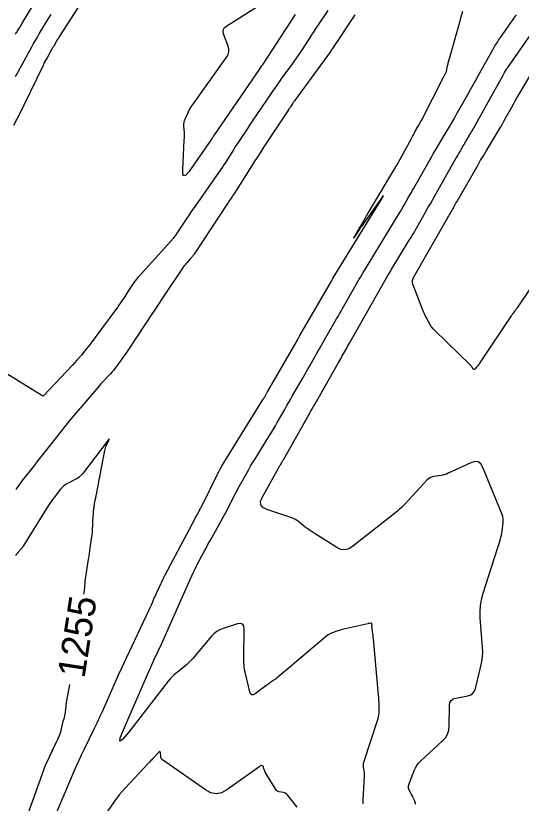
# Model space of a CAD drawing. Extents: x 658976 to 668726, y 639543 to 647196.
# Drawn here: x 661779.3 to 661889.7, y 641240.6 to 641412.7 of the extents above; entities that cross this region are included whole.
import ezdxf

# ---------------------------------------------------------------- set-up
doc = ezdxf.new("R2010")
doc.units = 0
for name, color, linetype in [('Ex_Contour Labels', 7, 'Continuous'), ('Ex_Major Contours', 7, 'Continuous'), ('Ex_Minor Contours', 7, 'Continuous')]:
    doc.layers.add(name, color=color, linetype=linetype)

msp = doc.modelspace()

# ---------------------------------------------------------------- linework, layer by layer
at = {"layer": 'Ex_Major Contours'}
for points in [[(661779.23, 641408.63), (661779.33, 641408.82), (661779.45, 641409.01), (661779.56, 641409.2), (661779.68, 641409.39), (661780.16, 641410.14), (661780.27, 641410.32), (661780.39, 641410.51), (661780.51, 641410.7), (661780.62, 641410.89), (661783.99, 641416.52)], [(661794.12, 641286.29), (661794.27, 641287.14), (661794.31, 641287.34), (661794.34, 641287.54), (661794.36, 641287.74), (661794.38, 641287.95), (661794.44, 641288.76), (661794.45, 641288.96), (661794.47, 641289.16), (661794.5, 641289.37), (661794.53, 641289.57), (661795.19, 641293.91), (661795.29, 641294.53), (661795.38, 641295.15), (661795.47, 641295.78), (661795.55, 641296.4), (661796.01, 641299.73), (661796.03, 641299.94), (661796.05, 641300.14), (661796.06, 641300.34), (661796.07, 641300.55), (661796.1, 641301.36), (661796.11, 641301.57), (661796.12, 641301.77), (661796.13, 641301.97), (661796.14, 641302.18), (661796.37, 641305.05), (661796.39, 641305.28), (661796.42, 641305.51), (661796.45, 641305.73), (661796.49, 641305.95), (661796.66, 641306.85), (661796.7, 641307.07), (661796.75, 641307.29), (661796.79, 641307.52), (661796.83, 641307.74), (661797.33, 641310.35), (661797.42, 641310.86), (661797.52, 641311.37), (661797.62, 641311.87), (661797.72, 641312.38), (661798.73, 641317.67), (661798.8, 641317.96), (661798.88, 641318.25), (661798.98, 641318.53), (661799.1, 641318.8), (661799.6, 641319.89), (661799.69, 641320.1), (661799.7, 641320.18), (661799.63, 641320.13), (661799.49, 641319.96), (661793.92, 641312.63), (661793.6, 641312.25), (661793.24, 641311.92), (661792.84, 641311.62), (661792.41, 641311.37), (661790.61, 641310.45), (661790.18, 641310.2), (661789.78, 641309.91), (661789.41, 641309.58), (661789.08, 641309.2), (661787.65, 641307.38), (661787.31, 641306.94), (661786.99, 641306.5), (661786.67, 641306.04), (661786.38, 641305.57), (661780.9, 641296.78), (661780.78, 641296.59), (661780.65, 641296.41), (661780.52, 641296.24), (661780.38, 641296.07), (661779.81, 641295.41), (661779.67, 641295.24), (661779.53, 641295.07), (661779.39, 641294.9), (661779.25, 641294.73)], [(661781.25, 641236.28), (661785.79, 641248.89), (661785.81, 641248.94), (661785.83, 641248.99), (661785.85, 641249.04), (661785.87, 641249.09), (661785.96, 641249.29), (661785.98, 641249.34), (661786, 641249.39), (661786.03, 641249.44), (661786.05, 641249.49), (661787.39, 641252.24), (661787.4, 641252.26), (661787.41, 641252.28), (661787.4, 641252.27), (661787.38, 641252.24), (661787.27, 641252.11), (661787.25, 641252.08), (661787.24, 641252.08), (661787.24, 641252.09), (661787.26, 641252.12), (661788.26, 641254.09), (661788.37, 641254.32), (661788.48, 641254.54), (661788.57, 641254.77), (661788.67, 641255), (661789.03, 641255.95), (661789.11, 641256.17), (661789.18, 641256.39), (661789.23, 641256.62), (661789.29, 641256.84), (661789.5, 641257.9), (661789.53, 641258.05), (661789.57, 641258.2), (661789.62, 641258.36), (661789.66, 641258.51), (661789.86, 641259.11), (661789.9, 641259.26), (661789.95, 641259.41), (661789.98, 641259.57), (661790.01, 641259.72), (661790.13, 641260.41), (661790.16, 641260.58), (661790.18, 641260.74), (661790.2, 641260.91), (661790.22, 641261.08), (661790.28, 641261.87), (661790.3, 641262.06), (661790.32, 641262.24), (661790.35, 641262.43), (661790.38, 641262.61), (661791.07, 641266.53)]]:
    msp.add_lwpolyline(points, dxfattribs=at)
at = {"layer": 'Ex_Minor Contours'}
for points in [[(661778.89, 641388.8), (661779.3, 641389.6), (661779.4, 641389.8), (661779.5, 641390), (661779.6, 641390.2), (661779.7, 641390.41), (661785.33, 641401.91), (661785.52, 641402.29), (661785.71, 641402.66), (661785.91, 641403.03), (661786.11, 641403.4), (661787.02, 641405.07), (661787.17, 641405.34), (661787.33, 641405.61), (661787.48, 641405.88), (661787.64, 641406.14), (661788.27, 641407.2), (661788.43, 641407.46), (661788.59, 641407.72), (661788.75, 641407.98), (661788.92, 641408.24), (661794.52, 641416.94)], [(661840.32, 641412.99), (661833.08, 641401.88), (661833.04, 641401.82), (661833, 641401.76), (661832.96, 641401.7), (661832.92, 641401.64), (661832.75, 641401.42), (661832.71, 641401.36), (661832.67, 641401.3), (661832.63, 641401.25), (661832.59, 641401.19), (661822.57, 641386.49), (661822.54, 641386.43), (661822.5, 641386.37), (661822.46, 641386.32), (661822.43, 641386.26), (661822.26, 641386.01), (661822.23, 641385.97), (661822.2, 641385.92), (661822.18, 641385.88), (661822.15, 641385.83), (661822.03, 641385.66), (661822.01, 641385.61), (661821.98, 641385.57), (661821.95, 641385.52), (661821.92, 641385.48), (661817.06, 641378.56), (661816.45, 641377.84), (661816.03, 641377.67), (661815.8, 641378.06), (661815.77, 641379.01), (661816.1, 641385.6), (661816.12, 641385.98), (661816.12, 641386.37), (661816.12, 641386.75), (661816.11, 641387.13), (661816.03, 641388.65), (661816.03, 641389.03), (661816.08, 641389.4), (661816.17, 641389.76), (661816.3, 641390.11), (661816.99, 641391.67), (661817.17, 641392.04), (661817.36, 641392.4), (661817.58, 641392.75), (661817.81, 641393.09), (661825.39, 641403.69), (661825.71, 641404.25), (661825.86, 641404.83), (661825.86, 641405.42), (661825.69, 641406.04), (661824.73, 641408.55), (661824.59, 641409.14), (661824.65, 641409.67), (661824.91, 641410.12), (661825.38, 641410.52), (661831.73, 641414.52)], [(661847.46, 641413.86), (661845.34, 641410.68), (661844.86, 641409.95), (661844.38, 641409.23), (661843.9, 641408.5), (661843.43, 641407.77), (661841.53, 641404.86), (661841.05, 641404.13), (661840.56, 641403.42), (661840.06, 641402.7), (661839.56, 641402), (661837.37, 641399.01), (661836.84, 641398.27), (661836.32, 641397.53), (661835.8, 641396.79), (661835.28, 641396.04), (661831.7, 641390.79), (661831.24, 641390.11), (661830.78, 641389.43), (661830.33, 641388.74), (661829.88, 641388.06), (661827.88, 641385.01), (661827.53, 641384.47), (661827.17, 641383.93), (661826.82, 641383.38), (661826.48, 641382.83), (661825.09, 641380.64), (661824.74, 641380.09), (661824.38, 641379.55), (661824.02, 641379.01), (661823.65, 641378.48), (661818.46, 641371.1), (661817.97, 641370.4), (661817.49, 641369.69), (661817.01, 641368.98), (661816.53, 641368.26), (661814.64, 641365.4), (661814.16, 641364.7), (661813.65, 641364.01), (661813.11, 641363.35), (661812.54, 641362.7), (661806.22, 641355.79), (661805.92, 641355.45), (661805.64, 641355.1), (661805.36, 641354.73), (661805.1, 641354.36), (661804.09, 641352.85), (661803.83, 641352.47), (661803.58, 641352.09), (661803.33, 641351.71), (661803.08, 641351.33), (661802.02, 641349.73), (661801.75, 641349.34), (661801.49, 641348.95), (661801.21, 641348.57), (661800.93, 641348.18), (661795.51, 641340.92), (661794.58, 641339.71), (661793.62, 641338.53), (661792.62, 641337.38), (661791.59, 641336.26), (661785.31, 641329.6), (661785.3, 641329.59), (661785.27, 641329.55), (661785.27, 641329.55), (661785.26, 641329.55), (661785.26, 641329.55), (661785.25, 641329.55), (661785.09, 641329.65), (661785.06, 641329.67), (661785.03, 641329.69), (661785, 641329.71), (661784.98, 641329.72), (661761.21, 641344.31)], [(661779.25, 641399.39), (661779.56, 641399.99), (661779.89, 641400.59), (661782.78, 641405.87), (661783.19, 641406.59), (661783.59, 641407.31), (661784.01, 641408.03), (661784.43, 641408.74), (661786.42, 641412.06), (661786.7, 641412.53), (661786.99, 641412.99)], [(661853.39, 641412.92), (661848.45, 641405.5), (661848.42, 641405.45), (661848.39, 641405.41), (661848.36, 641405.36), (661848.34, 641405.32), (661848.22, 641405.14), (661848.19, 641405.09), (661848.16, 641405.05), (661848.13, 641405.01), (661848.1, 641404.96), (661840.17, 641394.09), (661840.05, 641393.94), (661839.94, 641393.78), (661839.83, 641393.62), (661839.72, 641393.46), (661839.28, 641392.81), (661839.17, 641392.65), (661839.06, 641392.49), (661838.95, 641392.33), (661838.84, 641392.16), (661833.5, 641384.01), (661832.82, 641382.97), (661832.14, 641381.93), (661831.47, 641380.88), (661830.8, 641379.83), (661827.06, 641373.9), (661826.94, 641373.71), (661826.81, 641373.52), (661826.69, 641373.33), (661826.56, 641373.15), (661826.04, 641372.41), (661825.91, 641372.23), (661825.78, 641372.04), (661825.66, 641371.86), (661825.53, 641371.67), (661818.23, 641360.59), (661818.05, 641360.33), (661817.86, 641360.08), (661817.67, 641359.84), (661817.46, 641359.61), (661816.62, 641358.69), (661816.41, 641358.45), (661816.22, 641358.21), (661816.03, 641357.96), (661815.85, 641357.71), (661811.27, 641350.86), (661810.45, 641349.63), (661809.63, 641348.41), (661808.81, 641347.18), (661807.99, 641345.94), (661803.46, 641339.09), (661803.16, 641338.65), (661802.85, 641338.21), (661802.54, 641337.77), (661802.23, 641337.34), (661800.9, 641335.57), (661800.6, 641335.17), (661800.28, 641334.78), (661799.96, 641334.41), (661799.62, 641334.04), (661798.25, 641332.58), (661797.9, 641332.22), (661797.57, 641331.85), (661797.24, 641331.47), (661796.91, 641331.09), (661792.43, 641325.86), (661791.6, 641324.89), (661790.79, 641323.91), (661789.99, 641322.92), (661789.2, 641321.92), (661785.62, 641317.37), (661785.05, 641316.64), (661784.48, 641315.92), (661783.91, 641315.19), (661783.34, 641314.47), (661780.67, 641311.09), (661780.3, 641310.6), (661779.94, 641310.11), (661779.6, 641309.6), (661779.26, 641309.08)], [(661788, 641238.12), (661792.04, 641247.56), (661792.57, 641248.77), (661793.11, 641249.97), (661793.66, 641251.16), (661794.23, 641252.34), (661796.57, 641257.13), (661797.12, 641258.28), (661797.67, 641259.44), (661798.2, 641260.61), (661798.72, 641261.78), (661800.77, 641266.48), (661801.29, 641267.65), (661801.81, 641268.82), (661802.35, 641269.98), (661802.89, 641271.14), (661808.34, 641282.71), (661808.63, 641283.34), (661808.92, 641283.96), (661809.2, 641284.59), (661809.48, 641285.21), (661810.6, 641287.73), (661810.88, 641288.35), (661811.18, 641288.98), (661811.48, 641289.59), (661811.8, 641290.2), (661818.45, 641302.82), (661818.56, 641303.02), (661818.67, 641303.22), (661818.78, 641303.42), (661818.89, 641303.62), (661819.34, 641304.43), (661819.45, 641304.63), (661819.56, 641304.83), (661819.67, 641305.03), (661819.77, 641305.24), (661823.68, 641313.11), (661823.73, 641313.22), (661823.79, 641313.33), (661823.85, 641313.44), (661823.91, 641313.55), (661824.14, 641313.97), (661824.2, 641314.08), (661824.27, 641314.19), (661824.33, 641314.29), (661824.39, 641314.4), (661833.36, 641328.9), (661833.45, 641329.04), (661833.52, 641329.17), (661833.6, 641329.3), (661833.68, 641329.43), (661833.98, 641329.97), (661834.06, 641330.11), (661834.14, 641330.24), (661834.21, 641330.38), (661834.29, 641330.51), (661840.8, 641341.77), (661840.85, 641341.85), (661840.9, 641341.94), (661840.94, 641342.02), (661840.99, 641342.11), (661841.18, 641342.45), (661841.23, 641342.53), (661841.28, 641342.62), (661841.33, 641342.7), (661841.38, 641342.78), (661848.25, 641354.66), (661848.27, 641354.7), (661848.29, 641354.74), (661848.31, 641354.78), (661848.34, 641354.82), (661848.59, 641355.26), (661848.61, 641355.29), (661848.62, 641355.33), (661848.64, 641355.36), (661848.66, 641355.39), (661859.08, 641372.45), (661859.48, 641373.12), (661859.59, 641373.35), (661859.42, 641373.16), (661858.96, 641372.52), (661854.74, 641366.53), (661854.63, 641366.38), (661854.53, 641366.23), (661854.43, 641366.08), (661854.33, 641365.93), (661853.32, 641364.38), (661853.16, 641364.14), (661853.1, 641364.07), (661853.14, 641364.15), (661853.28, 641364.4), (661854.56, 641366.61), (661854.71, 641366.87), (661854.85, 641367.12), (661855, 641367.38), (661855.15, 641367.64), (661855.73, 641368.67), (661855.88, 641368.93), (661856.03, 641369.18), (661856.18, 641369.44), (661856.33, 641369.69), (661862.52, 641380.05), (661862.91, 641380.7), (661863.28, 641381.35), (661863.65, 641382.01), (661864.01, 641382.67), (661865.8, 641386.01), (661865.98, 641386.33), (661866.15, 641386.65), (661866.32, 641386.96), (661866.5, 641387.28), (661867.21, 641388.54), (661867.38, 641388.86), (661867.56, 641389.17), (661867.73, 641389.49), (661867.89, 641389.81), (661872.75, 641399.24), (661872.82, 641399.38), (661872.89, 641399.52), (661872.96, 641399.66), (661873.03, 641399.81), (661873.29, 641400.38), (661873.36, 641400.52), (661873.41, 641400.67), (661873.45, 641400.82), (661873.49, 641400.98), (661873.69, 641401.95), (661873.73, 641402.17), (661873.78, 641402.38), (661873.84, 641402.59), (661873.89, 641402.8), (661876.13, 641410.79), (661876.24, 641411.16), (661876.34, 641411.52), (661876.45, 641411.89), (661876.55, 641412.25), (661876.99, 641413.71)], [(661855.2, 641240.42), (661855.18, 641240.71), (661855.18, 641240.99), (661855.18, 641241.27), (661855.48, 641246.54), (661855.49, 641246.79), (661855.48, 641247.05), (661855.46, 641247.3), (661855.43, 641247.55), (661855.28, 641248.56), (661855.25, 641248.82), (661855.26, 641249.07), (661855.29, 641249.31), (661855.35, 641249.56), (661858.43, 641259.08), (661858.55, 641259.49), (661858.63, 641259.91), (661858.67, 641260.33), (661858.68, 641260.76), (661858.65, 641262.48), (661858.64, 641262.91), (661858.62, 641263.34), (661858.6, 641263.77), (661858.56, 641264.2), (661857.42, 641276.49), (661857.4, 641276.78), (661857.36, 641277.06), (661857.33, 641277.35), (661857.3, 641277.63), (661857.09, 641279.26), (661857.09, 641279.3), (661857.09, 641279.34), (661857.09, 641279.38), (661857.09, 641279.42), (661857.12, 641279.58), (661857.12, 641279.62), (661857.12, 641279.66), (661857.12, 641279.69), (661857.11, 641279.73), (661857.08, 641279.88), (661857.06, 641279.91), (661857.04, 641279.94), (661857.02, 641279.95), (661856.98, 641279.95), (661856.53, 641279.87), (661856.44, 641279.85), (661856.35, 641279.83), (661856.26, 641279.82), (661856.17, 641279.8), (661850.95, 641278.62), (661850.62, 641278.54), (661850.3, 641278.45), (661849.98, 641278.36), (661849.67, 641278.25), (661848.41, 641277.81), (661848.1, 641277.68), (661847.81, 641277.53), (661847.54, 641277.36), (661847.27, 641277.16), (661841.16, 641272.02), (661840.66, 641271.6), (661840.15, 641271.17), (661839.65, 641270.74), (661839.15, 641270.32), (661836.55, 641268.1), (661836.34, 641267.92), (661836.13, 641267.76), (661835.92, 641267.6), (661835.7, 641267.45), (661834.81, 641266.85), (661834.59, 641266.7), (661834.37, 641266.54), (661834.15, 641266.39), (661833.93, 641266.23), (661831.59, 641264.49), (661831.16, 641264.25), (661830.83, 641264.25), (661830.57, 641264.47), (661830.4, 641264.92), (661829.46, 641268.9), (661829.29, 641269.75), (661829.17, 641270.61), (661829.1, 641271.47), (661829.09, 641272.34), (661829.21, 641278.63), (661829.13, 641279.31), (661828.85, 641279.72), (661828.38, 641279.87), (661827.71, 641279.76), (661824.62, 641278.78), (661823.88, 641278.49), (661823.21, 641278.11), (661822.59, 641277.63), (661822.04, 641277.06), (661817.86, 641272.14), (661817.46, 641271.69), (661817.04, 641271.26), (661816.6, 641270.85), (661816.14, 641270.46), (661814.24, 641268.95), (661813.78, 641268.57), (661813.35, 641268.15), (661812.94, 641267.71), (661812.56, 641267.24), (661803.88, 641256), (661802.63, 641254.51), (661802.03, 641254.12), (661802.09, 641254.83), (661802.79, 641256.64), (661808.56, 641269.84), (661808.79, 641270.34), (661809.01, 641270.85), (661809.24, 641271.35), (661809.47, 641271.84), (661810.41, 641273.83), (661810.64, 641274.33), (661810.87, 641274.83), (661811.1, 641275.33), (661811.33, 641275.84), (661817.38, 641289.49), (661817.73, 641290.27), (661818.1, 641291.04), (661818.48, 641291.81), (661818.87, 641292.57), (661820.46, 641295.59), (661820.87, 641296.35), (661821.27, 641297.1), (661821.68, 641297.85), (661822.1, 641298.6), (661824.63, 641303.1), (661824.91, 641303.61), (661825.19, 641304.12), (661825.46, 641304.63), (661825.72, 641305.15), (661826.75, 641307.23), (661827.01, 641307.75), (661827.28, 641308.27), (661827.55, 641308.78), (661827.83, 641309.29), (661829.75, 641312.73), (661830.17, 641313.48), (661830.6, 641314.21), (661831.03, 641314.94), (661831.48, 641315.67), (661834.72, 641320.91), (661835.15, 641321.62), (661835.58, 641322.33), (661836, 641323.05), (661836.41, 641323.77), (661838.04, 641326.65), (661838.45, 641327.37), (661838.86, 641328.09), (661839.27, 641328.81), (661839.68, 641329.53), (661842.05, 641333.64), (661842.42, 641334.28), (661842.79, 641334.92), (661843.16, 641335.56), (661843.52, 641336.2), (661844.98, 641338.78), (661845.34, 641339.42), (661845.71, 641340.06), (661846.08, 641340.7), (661846.45, 641341.34), (661849.38, 641346.42), (661849.71, 641346.99), (661850.04, 641347.56), (661850.37, 641348.13), (661850.69, 641348.7), (661854.31, 641355.09), (661854.59, 641355.58), (661854.88, 641356.07), (661855.17, 641356.55), (661855.46, 641357.04), (661863.05, 641369.47), (661863.32, 641369.92), (661863.6, 641370.38), (661863.86, 641370.84), (661864.13, 641371.3), (661865.19, 641373.15), (661865.45, 641373.61), (661865.72, 641374.08), (661865.98, 641374.54), (661866.25, 641375), (661869.53, 641380.77), (661870.02, 641381.63), (661870.51, 641382.49), (661871.01, 641383.34), (661871.52, 641384.19), (661873.54, 641387.59), (661874.04, 641388.44), (661874.54, 641389.3), (661875.04, 641390.16), (661875.52, 641391.02), (661878.06, 641395.51), (661878.64, 641396.55), (661879.22, 641397.59), (661879.8, 641398.63), (661880.38, 641399.67), (661883.59, 641405.42), (661883.97, 641406.08), (661884.36, 641406.72), (661884.77, 641407.35), (661885.19, 641407.97), (661886.93, 641410.43), (661887.37, 641411.05), (661887.8, 641411.67), (661888.23, 641412.28), (661888.67, 641412.9)], [(661866.63, 641240.38), (661866.6, 641240.61), (661866.53, 641240.83), (661866.45, 641241.04), (661866.04, 641241.89), (661865.93, 641242.1), (661865.83, 641242.31), (661865.73, 641242.52), (661865.63, 641242.73), (661865.18, 641243.66), (661865.1, 641243.89), (661865.07, 641244.11), (661865.08, 641244.34), (661865.15, 641244.58), (661866.33, 641247.7), (661866.59, 641248.28), (661866.91, 641248.81), (661867.29, 641249.31), (661867.73, 641249.77), (661872.51, 641254.2), (661873.14, 641254.9), (661873.59, 641255.68), (661873.87, 641256.54), (661873.97, 641257.47), (661874.05, 641261.95), (661874.14, 641262.56), (661874.4, 641263.03), (661874.82, 641263.37), (661875.4, 641263.57), (661878.07, 641264.08), (661878.67, 641264.28), (661879.15, 641264.6), (661879.5, 641265.07), (661879.72, 641265.66), (661880.91, 641270.52), (661881.12, 641271.56), (661881.24, 641272.6), (661881.29, 641273.64), (661881.25, 641274.7), (661880.76, 641280.99), (661880.71, 641282.38), (661880.81, 641283.76), (661881.03, 641285.12), (661881.39, 641286.47), (661885.16, 641298.26), (661885.29, 641298.71), (661885.4, 641299.16), (661885.48, 641299.61), (661885.55, 641300.07), (661885.77, 641301.92), (661885.79, 641302.37), (661885.76, 641302.82), (661885.67, 641303.27), (661885.52, 641303.7), (661881.35, 641313.95), (661880.89, 641314.74), (661880.29, 641315.18), (661879.55, 641315.26), (661878.68, 641315), (661873.78, 641312.69), (661873.4, 641312.52), (661873, 641312.39), (661872.6, 641312.28), (661872.19, 641312.21), (661870.53, 641311.96), (661870.13, 641311.87), (661869.77, 641311.72), (661869.44, 641311.5), (661869.14, 641311.22), (661864.38, 641306.03), (661863.98, 641305.61), (661863.56, 641305.2), (661863.13, 641304.82), (661862.68, 641304.44), (661852.87, 641296.65), (661852.03, 641296.14), (661851.18, 641295.94), (661850.31, 641296.05), (661849.43, 641296.46), (661844.46, 641299.61), (661844.27, 641299.73), (661844.07, 641299.86), (661843.88, 641299.99), (661843.68, 641300.12), (661842.91, 641300.64), (661842.72, 641300.77), (661842.53, 641300.91), (661842.35, 641301.05), (661842.17, 641301.19), (661840.96, 641302.2), (661840.69, 641302.4), (661840.41, 641302.58), (661840.11, 641302.73), (661839.79, 641302.85), (661834.11, 641304.75), (661833.25, 641305.18), (661832.8, 641305.77), (661832.74, 641306.51), (661833.08, 641307.4), (661836.72, 641313.94), (661836.81, 641314.1), (661836.9, 641314.25), (661836.99, 641314.41), (661837.09, 641314.56), (661837.47, 641315.17), (661837.56, 641315.33), (661837.65, 641315.48), (661837.75, 641315.64), (661837.84, 641315.8), (661843.29, 641325.46), (661843.43, 641325.71), (661843.57, 641325.95), (661843.71, 641326.19), (661843.85, 641326.44), (661844.41, 641327.41), (661844.55, 641327.65), (661844.69, 641327.89), (661844.83, 641328.14), (661844.97, 641328.38), (661849.73, 641336.79), (661849.93, 641337.15), (661850.14, 641337.51), (661850.34, 641337.87), (661850.55, 641338.23), (661851.38, 641339.66), (661851.58, 641340.01), (661851.79, 641340.37), (661851.99, 641340.73), (661852.2, 641341.09), (661860.59, 641355.89), (661860.85, 641356.35), (661861.12, 641356.81), (661861.39, 641357.27), (661861.67, 641357.72), (661865.03, 641363.24), (661865.32, 641363.7), (661865.6, 641364.17), (661865.87, 641364.64), (661866.15, 641365.12), (661868.79, 641369.74), (661869.33, 641370.67), (661869.86, 641371.6), (661870.39, 641372.53), (661870.91, 641373.46), (661875.46, 641381.47), (661875.65, 641381.8), (661875.84, 641382.14), (661876.04, 641382.47), (661876.23, 641382.8), (661877.06, 641384.26), (661877.22, 641384.54), (661877.38, 641384.81), (661877.54, 641385.08), (661877.7, 641385.36), (661878.36, 641386.45), (661878.52, 641386.72), (661878.68, 641387), (661878.84, 641387.28), (661879, 641387.55), (661885.75, 641399.72), (661885.83, 641399.86), (661885.91, 641400), (661886, 641400.14), (661886.08, 641400.29), (661886.42, 641400.85), (661886.5, 641400.99), (661886.59, 641401.13), (661886.68, 641401.26), (661886.77, 641401.4), (661892.86, 641410.04)], [(661894.93, 641357.92), (661888.81, 641348.84), (661888.71, 641348.69), (661888.61, 641348.55), (661888.5, 641348.4), (661888.39, 641348.26), (661887.95, 641347.68), (661887.84, 641347.54), (661887.73, 641347.4), (661887.63, 641347.25), (661887.53, 641347.1), (661880.63, 641336.78), (661880.58, 641336.7), (661880.53, 641336.63), (661880.48, 641336.55), (661880.42, 641336.48), (661880.2, 641336.18), (661880.14, 641336.11), (661880.08, 641336.04), (661880.02, 641335.96), (661879.96, 641335.89), (661879.56, 641335.43), (661879.48, 641335.36), (661879.4, 641335.34), (661879.32, 641335.37), (661879.25, 641335.45), (661878.94, 641335.94), (661878.86, 641336.06), (661878.77, 641336.17), (661878.68, 641336.27), (661878.58, 641336.37), (661870.77, 641343.96), (661870.48, 641344.26), (661870.21, 641344.59), (661869.97, 641344.93), (661869.75, 641345.3), (661868.93, 641346.8), (661868.73, 641347.18), (661868.55, 641347.56), (661868.38, 641347.95), (661868.22, 641348.35), (661866.06, 641354.02), (661865.96, 641354.39), (661865.95, 641354.76), (661866.02, 641355.11), (661866.17, 641355.47), (661867.33, 641357.51), (661867.35, 641357.54), (661867.36, 641357.56), (661867.38, 641357.59), (661867.39, 641357.61), (661867.57, 641357.91), (661867.59, 641357.94), (661867.6, 641357.96), (661867.62, 641357.99), (661867.63, 641358.01), (661873.67, 641368.56), (661873.83, 641368.84), (661873.99, 641369.13), (661874.16, 641369.41), (661874.32, 641369.7), (661874.97, 641370.84), (661875.13, 641371.13), (661875.3, 641371.41), (661875.46, 641371.7), (661875.62, 641371.98), (661879.7, 641379.11), (661880.27, 641380.11), (661880.85, 641381.11), (661881.44, 641382.1), (661882.03, 641383.09), (661884.87, 641387.82), (661885.23, 641388.43), (661885.59, 641389.04), (661885.94, 641389.65), (661886.29, 641390.27), (661887.66, 641392.73), (661888, 641393.35), (661888.35, 641393.96), (661888.71, 641394.57), (661889.06, 641395.18), (661892.06, 641400.19)], [(661840.77, 641239.71), (661838.58, 641242.45), (661838.42, 641242.62), (661838.23, 641242.75), (661838.03, 641242.85), (661837.8, 641242.91), (661836.85, 641243.07), (661836.62, 641243.13), (661836.43, 641243.23), (661836.26, 641243.38), (661836.12, 641243.56), (661833.8, 641247.39), (661833.73, 641247.51), (661833.67, 641247.64), (661833.62, 641247.77), (661833.57, 641247.9), (661833.36, 641248.58), (661833.33, 641248.64), (661833.3, 641248.69), (661833.25, 641248.72), (661833.2, 641248.75), (661832.94, 641248.82), (661832.89, 641248.83), (661832.83, 641248.83), (661832.78, 641248.81), (661832.74, 641248.77), (661832.57, 641248.59), (661832.53, 641248.54), (661832.48, 641248.5), (661832.44, 641248.46), (661832.39, 641248.43), (661825.43, 641243.48), (661824.25, 641242.85), (661823.07, 641242.64), (661821.89, 641242.85), (661820.71, 641243.47), (661811.34, 641250.09), (661811.18, 641250.22), (661811.06, 641250.38), (661810.99, 641250.56), (661810.95, 641250.77), (661810.87, 641251.63), (661810.84, 641251.8), (661810.77, 641251.88), (661810.67, 641251.86), (661810.54, 641251.75), (661809.26, 641250.37), (661808.99, 641250.09), (661808.73, 641249.81), (661808.47, 641249.53), (661808.21, 641249.25), (661803.17, 641243.84), (661802.52, 641243.11), (661801.9, 641242.37), (661801.3, 641241.6), (661800.74, 641240.81), (661798.26, 641237.24)]]:
    msp.add_lwpolyline(points, dxfattribs=at)

# ---------------------------------------------------------------- texts
at = {"layer": 'Ex_Contour Labels'}
msp.add_text('1255', height=6, rotation=81.2288, dxfattribs=at).set_placement((661794.29, 641267.72))

doc.saveas('drawing.dxf')
